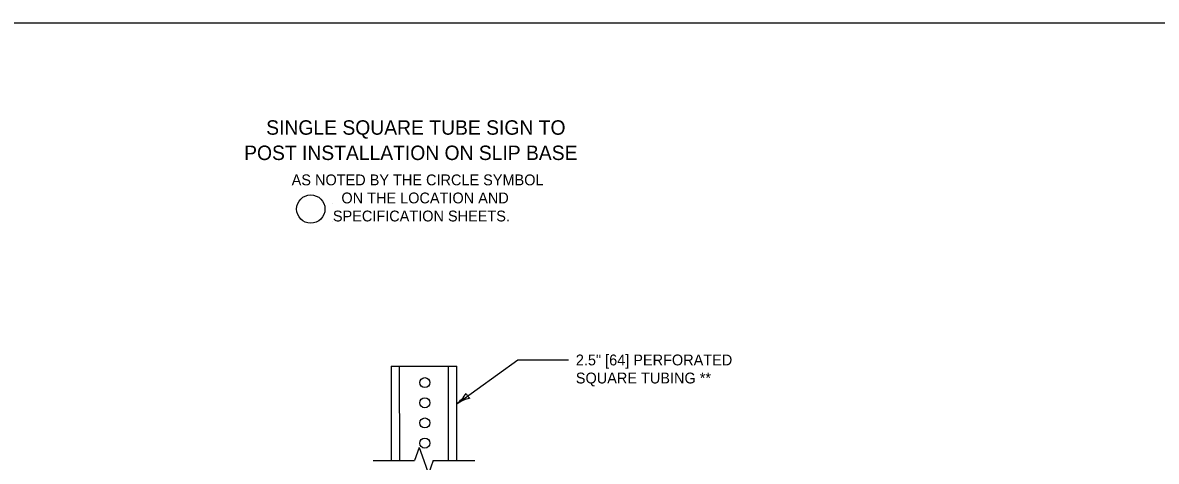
# Model space of a CAD drawing. Extents: x 49940 to 50043, y 49986 to 50011.
# Drawn here: x 50004.91 to 50011.19, y 49996.57 to 49999 of the extents above; entities that cross this region are included whole.
import ezdxf

# ---------------------------------------------------------------- set-up
doc = ezdxf.new("R2010")
doc.units = 0
for name, color, linetype in [('Level 1', 7, 'Continuous'), ('Level 2', 7, 'Continuous'), ('Level 3', 7, 'Continuous'), ('Level 4', 7, 'Continuous'), ('Level 6', 7, 'Continuous')]:
    doc.layers.add(name, color=color, linetype=linetype)

msp = doc.modelspace()

# ---------------------------------------------------------------- linework, layer by layer
at = {"layer": 'Level 1'}
msp.add_line((50006.9473, 49997.0981), (50007.3109, 49997.0981), dxfattribs=at)
msp.add_lwpolyline([(49999.3835, 49998.9992), (50016.7501, 49998.9992), (50016.7501, 49987.7988), (49999.3835, 49987.7988)], close=True, dxfattribs=at)
for points in [[(50006.9473, 49997.0981), (50006.9475, 49996.5743)], [(50007.3109, 49996.5744), (50007.3109, 49997.0981)]]:
    msp.add_lwpolyline(points, dxfattribs=at)
for centre in [(50007.134, 49997.0063), (50007.134, 49997.0063), (50007.134, 49996.8947), (50007.134, 49996.8947), (50007.134, 49996.7831), (50007.134, 49996.6715)]:
    msp.add_circle(centre, 0.0277, dxfattribs=at)
at = {"layer": 'Level 2'}
for p, q in [((50007.1826, 49998.4588), (50007.1826, 49998.4588)), ((50007.1826, 49998.3188), (50007.1826, 49998.3188)), ((50006.6212, 49997.9971), (50006.6212, 49997.9971)), ((50006.6224, 49997.8989), (50006.6224, 49997.8989))]:
    msp.add_line(p, q, dxfattribs=at)
msp.add_circle((50006.5024, 49997.9673), 0.0784, dxfattribs=at)
at = {"layer": 'Level 3'}
for p, q in [((50007.3109, 49996.8888), (50007.6494, 49997.1318)), ((50007.6494, 49997.1318), (50007.9307, 49997.1318))]:
    msp.add_line(p, q, dxfattribs=at)
for centre, radius, start, end in [((50007.1658, 49997.0711), 0.233, 308.50086, 327.75071), ((50007.415, 49996.9635), 0.0548, 197.81236, 233.53472), ((50007.433, 49996.703), 0.2223, 103.12956, 123.31306)]:
    msp.add_arc(centre, radius, start, end, dxfattribs=at)
at = {"layer": 'Level 4'}
for points in [[(50006.9928, 49997.0981), (50006.9929, 49996.5743)], [(50007.2655, 49996.5744), (50007.2655, 49997.0981)]]:
    msp.add_lwpolyline(points, dxfattribs=at)
at = {"layer": 'Level 6'}
for p, q in [((50007.1033, 49996.6475), (50007.0774, 49996.5744)), ((50007.1033, 49996.6475), (50007.1292, 49996.5744)), ((50006.8475, 49996.5743), (50007.0774, 49996.5743)), ((50007.1292, 49996.5744), (50007.1551, 49996.5013)), ((50007.181, 49996.5744), (50007.1551, 49996.5013)), ((50007.181, 49996.5744), (50007.4109, 49996.5744))]:
    msp.add_line(p, q, dxfattribs=at)

# ---------------------------------------------------------------- texts
at = {"layer": 'Level 2'}
for s, height, p in [('SINGLE SQUARE TUBE SIGN TO', 0.08, (50006.2551, 49998.3788)), ('POST INSTALLATION ON SLIP BASE', 0.0799, (50006.1331, 49998.2388)), ('AS NOTED BY THE CIRCLE SYMBOL', 0.06, (50006.3963, 49998.0988)), ('ON THE LOCATION AND', 0.06, (50006.6719, 49997.9988)), ('SPECIFICATION SHEETS.', 0.06, (50006.6248, 49997.8988)), ('2.5" [64] PERFORATED', 0.06, (50007.9707, 49997.1018)), ('SQUARE TUBING **', 0.06, (50007.9707, 49997.0018))]:
    msp.add_text(s, height=height, dxfattribs=at).set_placement(p)

doc.saveas('drawing.dxf')
